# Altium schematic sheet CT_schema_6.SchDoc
size 251 x 159 mm
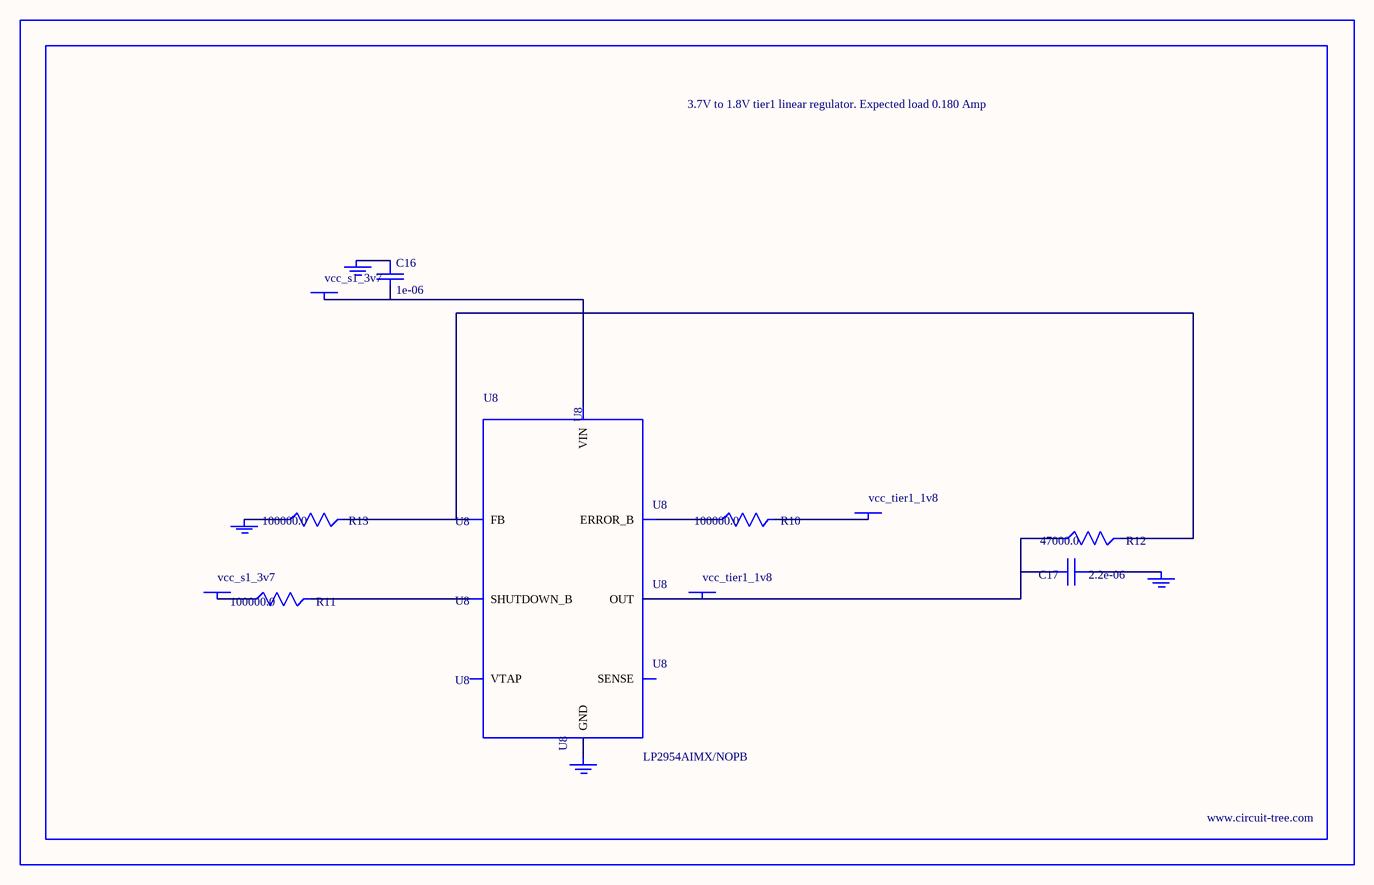
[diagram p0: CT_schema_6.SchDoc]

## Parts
BORDER5  (no value)
C16  1e-06  [EXV-9B]
C17  2.2e-06  [EXV-9B]
GND_INSTANCE_5_0  (no value)
GND_INSTANCE_5_1  (no value)
GND_INSTANCE_5_2  (no value)
GND_INSTANCE_5_3  (no value)
POWER_INSTANCE_5_0  vcc_s1_3v7
POWER_INSTANCE_5_1  vcc_tier1_1v8
POWER_INSTANCE_5_2  vcc_s1_3v7
POWER_INSTANCE_5_3  vcc_tier1_1v8
R10  100000.0  [R0603]
R11  100000.0  [R0603]
R12  47000.0  [R0603]
R13  100000.0  [R0603]
U8  LP2954AIMX/NOPB  [LP2954]

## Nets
NetC16_1: C16.1 GND_INSTANCE_5_2.0(GND)
NetC16_2: C16.2 POWER_INSTANCE_5_2.0(PWR) U8.8(VIN)
NetC17_1: C17.1 GND_INSTANCE_5_0.0(GND)
NetC17_2: C17.2 POWER_INSTANCE_5_3.0(PWR) R12.1 U8.1(OUT)
NetGND_INSTANCE_5_1_0: GND_INSTANCE_5_1.0(GND) R13.1
NetGND_INSTANCE_5_3_0: GND_INSTANCE_5_3.0(GND) U8.4(GND)
NetPOWER_INSTANCE_5_0_0: POWER_INSTANCE_5_0.0(PWR) R11.1
NetPOWER_INSTANCE_5_1_0: POWER_INSTANCE_5_1.0(PWR) R10.2
NetR10_1: R10.1 U8.5(ERROR_B)
NetR11_2: R11.2 U8.3(SHUTDOWN_B)
NetR12_2: R12.2 R13.2 U8.7(FB)

Not connected (* = marked no-connect by the designer): U8 2(SENSE) 6(VTAP)

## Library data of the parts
BORDER5 = BORDER_PAGE5
C16 = EDK105M050A9BAA
C17 = EDK225M050A9BAA
GND_INSTANCE_5_0-GND_INSTANCE_5_3 = GND
POWER_INSTANCE_5_0-POWER_INSTANCE_5_3 = PWR
R10 R11 R13 = RC0603JR-07100KL
R12 = RC0603JR-0747KL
